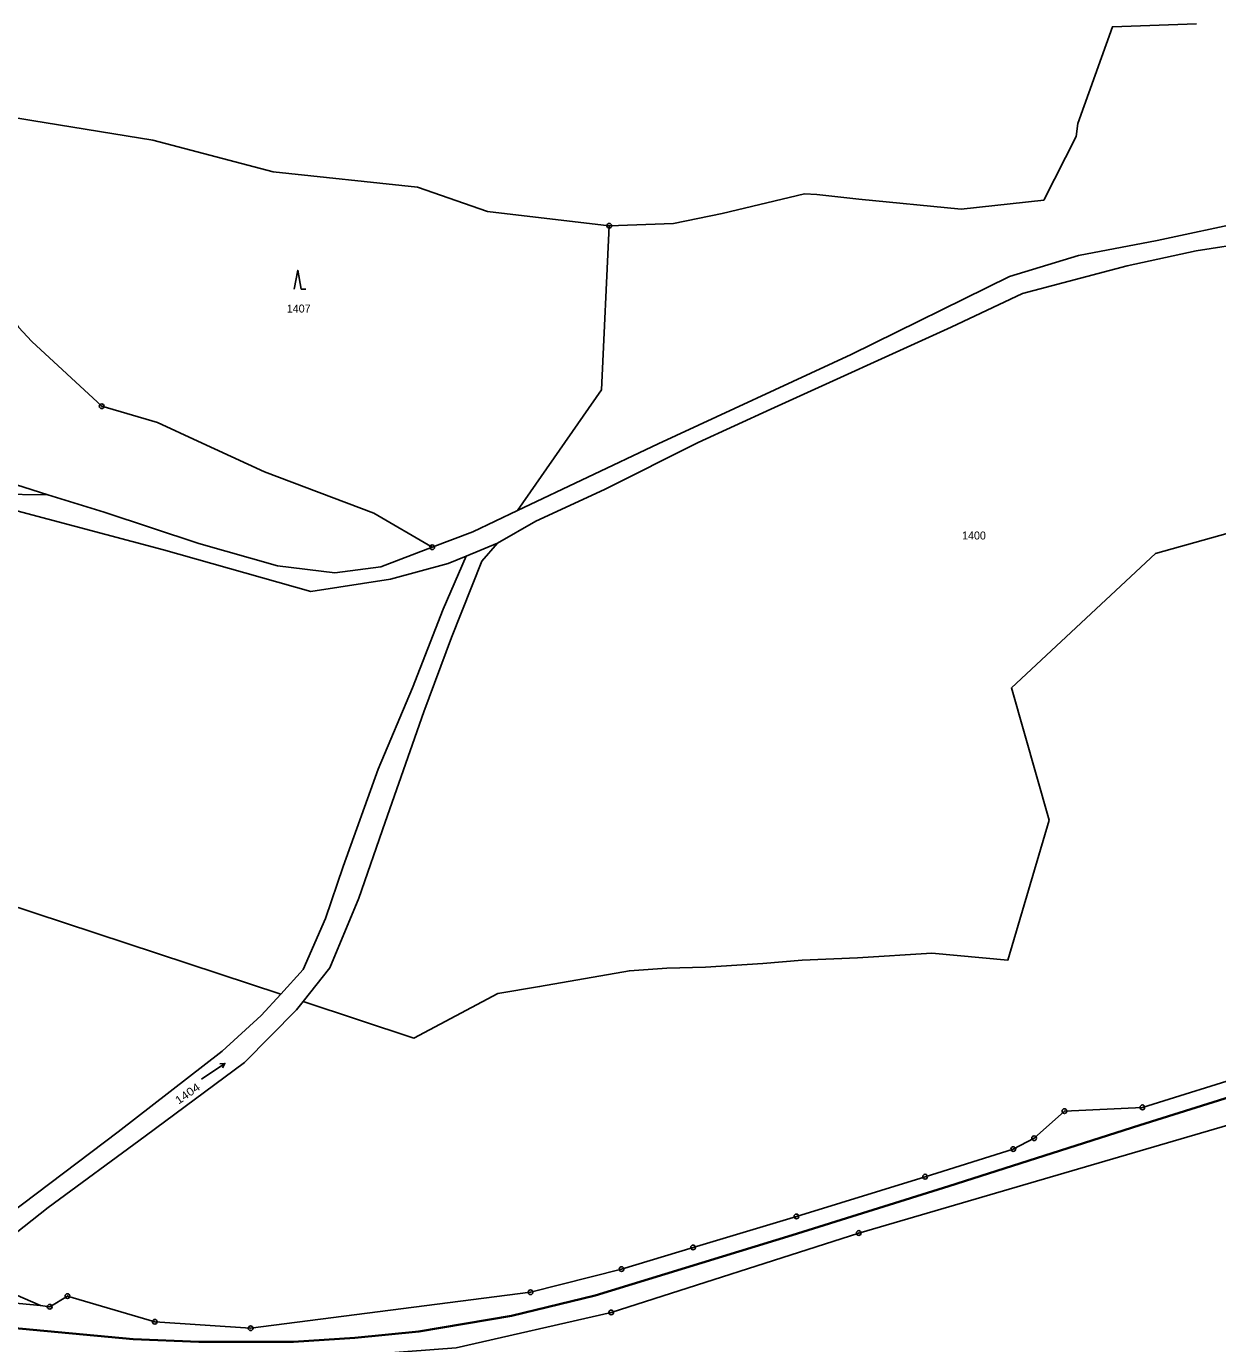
# Model space of a CAD drawing. Extents: x -872229 to -869198, y -1075981 to -1074329.
# Drawn here: x -870489.5 to -870236.3, y -1075493.1 to -1075213.2 of the extents above; entities that cross this region are included whole.
import ezdxf

# ---------------------------------------------------------------- set-up
doc = ezdxf.new("R2010")
doc.units = 0
doc.header["$LTSCALE"] = 0.68
for name, color, linetype, lineweight in [('1', 7, 'Continuous', 25), ('3', 7, 'Continuous', 25), ('6', 7, 'Continuous', 25), ('8', 7, 'Continuous', 25)]:
    doc.layers.add(name, color=color, linetype=linetype, lineweight=lineweight)
doc.layers.add('2', color=7, linetype='Continuous')

msp = doc.modelspace()

# ---------------------------------------------------------------- linework, layer by layer
at = {"layer": '1'}
for p, q in [((-870498.58, -1075312.54), (-870484.94, -1075312.75)), ((-870389.39, -1075322.98), (-870396.04, -1075325.73))]:
    msp.add_line(p, q, dxfattribs=at)
for points in [[(-870240.81, -1075212.65), (-870258.69, -1075213.29), (-870266.01, -1075233.81), (-870266.41, -1075236.59), (-870273.27, -1075250.11), (-870290.79, -1075252.03), (-870312.54, -1075249.92), (-870321.52, -1075248.92), (-870324.09, -1075248.79), (-870341.63, -1075252.94), (-870351.93, -1075255.06), (-870365.6, -1075255.58)], [(-870385.12, -1075316.07), (-870355.23, -1075301.89), (-870314.21, -1075282.93), (-870280.58, -1075266.36), (-870265.86, -1075261.9), (-870249.15, -1075258.69), (-870230, -1075254.57), (-870219.5, -1075254.87), (-870207.6, -1075253.65), (-870190, -1075251.81), (-870178.96, -1075255.5), (-870167.23, -1075255.17), (-870141.46, -1075254.46), (-870092.41, -1075254.3), (-870019.81, -1075254.06), (-869952.16, -1075254.08), (-869902.23, -1075254.21), (-869809.43, -1075253.56), (-869784.98, -1075249.67), (-869765.49, -1075244.15), (-869696.7, -1075225.43), (-869659.27, -1075213.75)], [(-870484.94, -1075312.75), (-870507.19, -1075305.67), (-870536.45, -1075296.46), (-870573.82, -1075284.57), (-870611.19, -1075272.67), (-870674.35, -1075252.89), (-870727.76, -1075235.26), (-870748.62, -1075229.44), (-870760.57, -1075227.08), (-870781.56, -1075223.68)], [(-870365.6, -1075255.58), (-870391.47, -1075252.55), (-870406.38, -1075247.4), (-870437.01, -1075244.1), (-870462.57, -1075237.4), (-870488.28, -1075233.18), (-870499.77, -1075231.3), (-870505.2, -1075231.6)], [(-870505.2, -1075231.6), (-870504.75, -1075249.5), (-870503.52, -1075255.95), (-870494.22, -1075272.65), (-870491.12, -1075277.11), (-870488.28, -1075280.14), (-870473.47, -1075293.92), (-870461.64, -1075297.33), (-870453.04, -1075301.3), (-870438.88, -1075307.81), (-870415.62, -1075316.62), (-870403.21, -1075323.85)], [(-870389.39, -1075322.98), (-870381.24, -1075318.31), (-870366.64, -1075311.61), (-870346.71, -1075301.64), (-870331.27, -1075294.54), (-870292.97, -1075277.13), (-870277.78, -1075269.99), (-870255.58, -1075264.06), (-870240.85, -1075260.92), (-870229.06, -1075259.04), (-870204.53, -1075257.8), (-870191.67, -1075256.42), (-870173.08, -1075260.11), (-870114.64, -1075257.88), (-870086.74, -1075257.68), (-870033.35, -1075257.7)], [(-870365.6, -1075255.58), (-870367.24, -1075290.43), (-870385.12, -1075316.07)], [(-870403.21, -1075323.85), (-870414.18, -1075328.04), (-870423.92, -1075329.31), (-870436.13, -1075327.84), (-870452.83, -1075323.05), (-870472.92, -1075316.43), (-870484.94, -1075312.75)], [(-870396.04, -1075325.73), (-870399.84, -1075327.3), (-870412.12, -1075330.68), (-870429.02, -1075333.26), (-870460.35, -1075324.44), (-870491.53, -1075316.1), (-870527.95, -1075326.37), (-870582.26, -1075344.32), (-870614.02, -1075355.21), (-870622.65, -1075357.15), (-870618.95, -1075358.37)], [(-870403.21, -1075323.85), (-870394.63, -1075320.58), (-870385.12, -1075316.07)], [(-870430.66, -1075420.4), (-870407.17, -1075428.14), (-870389.29, -1075418.67), (-870380.4, -1075417.19), (-870361.32, -1075413.84), (-870353.38, -1075413.31), (-870345.13, -1075413.08), (-870332.96, -1075412.32), (-870324.6, -1075411.61), (-870312.88, -1075411.08), (-870297.05, -1075410.08), (-870280.93, -1075411.62), (-870272.12, -1075381.88), (-870280.16, -1075353.72), (-870249.5, -1075325.23), (-870223.98, -1075318.04)], [(-870430.66, -1075420.4), (-870424.97, -1075413.23), (-870418.85, -1075398.4), (-870413.2, -1075382.3), (-870405.02, -1075358.84), (-870399.16, -1075343.05), (-870392.7, -1075326.81), (-870389.39, -1075322.98)], [(-870396.04, -1075325.73), (-870400.88, -1075337), (-870407.41, -1075353.74), (-870414.68, -1075371.04), (-870422.18, -1075391.71), (-870425.9, -1075402.71), (-870430.64, -1075413.55), (-870435.43, -1075418.82)], [(-870435.43, -1075418.82), (-870618.95, -1075358.37), (-870635.72, -1075362.14), (-870640.68, -1075391.97)], [(-869861.67, -1075370.56), (-869878.14, -1075367.33), (-869908.77, -1075363.47), (-869918.42, -1075363.79), (-869963.81, -1075365.31), (-869991.44, -1075371.29), (-870013.06, -1075376.14), (-870080.98, -1075397.47), (-870137.41, -1075416.91), (-870198.36, -1075434.14), (-870229.56, -1075445.28), (-870312.6, -1075469.56), (-870365.19, -1075486.42), (-870398.17, -1075493.93), (-870445.72, -1075497.57), (-870473.49, -1075498.03), (-870483.95, -1075496.85)], [(-870486.5, -1075484.99), (-870484.52, -1075485.24), (-870480.75, -1075482.95), (-870462.19, -1075488.41), (-870441.81, -1075489.8), (-870382.34, -1075482.14), (-870362.98, -1075477.23), (-870347.8, -1075472.63), (-870325.84, -1075466.04), (-870298.48, -1075457.59), (-870279.74, -1075451.72), (-870275.31, -1075449.42), (-870268.89, -1075443.67), (-870252.29, -1075442.86), (-870205.14, -1075428.17), (-870158.39, -1075411.62), (-870067.91, -1075385.07), (-870005.01, -1075365.55)], [(-870435.43, -1075418.82), (-870439.55, -1075423.36), (-870447.86, -1075430.89), (-870470, -1075448.07), (-870502.02, -1075472.23)], [(-870501.5, -1075478.06), (-870498.51, -1075474.88), (-870484.83, -1075464.11), (-870464.21, -1075448.97), (-870443.12, -1075433.33), (-870432.04, -1075422.14), (-870430.66, -1075420.4)], [(-870575.95, -1075474.7), (-870508.22, -1075480.79), (-870504.01, -1075483.3), (-870498.65, -1075483.83), (-870486.5, -1075484.99)], [(-870486.5, -1075484.99), (-870495.19, -1075481.2), (-870501.5, -1075478.06)]]:
    msp.add_lwpolyline(points, dxfattribs=at)
at = {"layer": '3'}
for p, q in [((-870431.06, -1075269.03), (-870430.064, -1075269.03)), ((-870447.294, -1075433.52), (-870447.824, -1075434.482))]:
    msp.add_line(p, q, dxfattribs=at)
for points in [[(-870431.06, -1075269.03), (-870431.81, -1075265.03), (-870432.56, -1075269.03)], [(-870452.268, -1075436.875), (-870447.294, -1075433.52), (-870448.384, -1075433.651)]]:
    msp.add_lwpolyline(points, dxfattribs=at)
at = {"layer": '6', "lineweight": 35}
for p, q in [((-870293.44, -1075459.6), (-870252.84, -1075446.64)), ((-870386.38, -1075487.12), (-870368.62, -1075482.81)), ((-870432.68, -1075492.68), (-870419.66, -1075491.85))]:
    msp.add_line(p, q, dxfattribs=at)
for points in [[(-870252.84, -1075446.64), (-870219.18, -1075436.13), (-870135.1, -1075409.54)], [(-870368.62, -1075482.81), (-870326.75, -1075470.04), (-870293.44, -1075459.6)], [(-870551.39, -1075483.38), (-870498.7, -1075489.12), (-870466.81, -1075492.11)], [(-870419.66, -1075491.85), (-870406.04, -1075490.5), (-870386.38, -1075487.12)], [(-870466.81, -1075492.11), (-870452.79, -1075492.7), (-870432.68, -1075492.68)]]:
    msp.add_lwpolyline(points, dxfattribs=at)
at = {"layer": '8'}
for centre, radius in [((-870365.6, -1075255.5799), 0.5), ((-870365.6, -1075255.5799), 0.0303), ((-870473.47, -1075293.9199), 0.5), ((-870473.47, -1075293.9199), 0.0303), ((-870403.21, -1075323.8499), 0.5), ((-870403.21, -1075323.8499), 0.0303), ((-870252.29, -1075442.8599), 0.5), ((-870268.89, -1075443.6699), 0.5), ((-870268.89, -1075443.6699), 0.0303), ((-870252.29, -1075442.8599), 0.0303), ((-870275.31, -1075449.4199), 0.5), ((-870275.31, -1075449.4199), 0.0303), ((-870279.74, -1075451.7199), 0.5), ((-870279.74, -1075451.7199), 0.0303), ((-870298.48, -1075457.5899), 0.5), ((-870298.48, -1075457.5899), 0.0303), ((-870325.84, -1075466.0399), 0.5), ((-870325.84, -1075466.0399), 0.0303), ((-870312.6, -1075469.5599), 0.5), ((-870312.6, -1075469.5599), 0.0303), ((-870347.8, -1075472.6299), 0.5), ((-870347.8, -1075472.6299), 0.0303), ((-870362.98, -1075477.2299), 0.5), ((-870362.98, -1075477.2299), 0.0303), ((-870382.34, -1075482.1399), 0.5), ((-870480.75, -1075482.9499), 0.5), ((-870480.75, -1075482.9499), 0.0303), ((-870382.34, -1075482.1399), 0.0303), ((-870484.52, -1075485.2399), 0.5), ((-870484.52, -1075485.2399), 0.0303), ((-870365.19, -1075486.4199), 0.5), ((-870365.19, -1075486.4199), 0.0303), ((-870462.19, -1075488.4099), 0.5), ((-870462.19, -1075488.4099), 0.0303), ((-870441.81, -1075489.7999), 0.5), ((-870441.81, -1075489.7999), 0.0303)]:
    msp.add_circle(centre, radius, dxfattribs=at)

# ---------------------------------------------------------------- texts
at = {"layer": '2'}
for s, p in [('1407', (-870434.13, -1075274.01)), ('1400', (-870290.63, -1075322.22))]:
    msp.add_text(s, height=1.7, dxfattribs=at).set_placement(p)
at = {"layer": '2', "width": 1.15}
msp.add_text('1404', height=1.7, rotation=35, dxfattribs=at).set_placement((-870457.132, -1075442.306))

doc.saveas('drawing.dxf')
